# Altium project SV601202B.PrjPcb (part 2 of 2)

## Sheet SV601202B_CONNECTOR.SchDoc
size 431 x 279 mm; Date: Not shown in title block; ApprovedBy: Not shown in title block; CheckedBy: Not shown in title block; Author: Not shown in title block; CompanyName: Not shown in title block; Engineer: Not shown in title block; Organization: Not shown in title block; Address1: Not shown in title block; Address2: Not shown in title block; Address3: Not shown in title block; Address4: Not shown in title block; DocumentNumber: 1; Revision: Use project parameter SCH_Rev; SheetNumber: 2; SheetTotal: 3; PageSetup: Record=PageOptions¦CenterHorizontal=True¦CenterVertical=True¦PrintScale=1.00¦XCorrection=1.00¦YCorrection=1.00¦PrintKind=0¦BorderSize=5000000¦LeftOffset=0¦BottomOffset=0¦Orientation=2¦PaperLength=1000¦PaperWidth=1000¦Scale=100¦PaperSource=15¦PrintQuality=600¦MediaType=1¦DitherType=10¦PaperKind=Letter¦PrintScaleMode=1
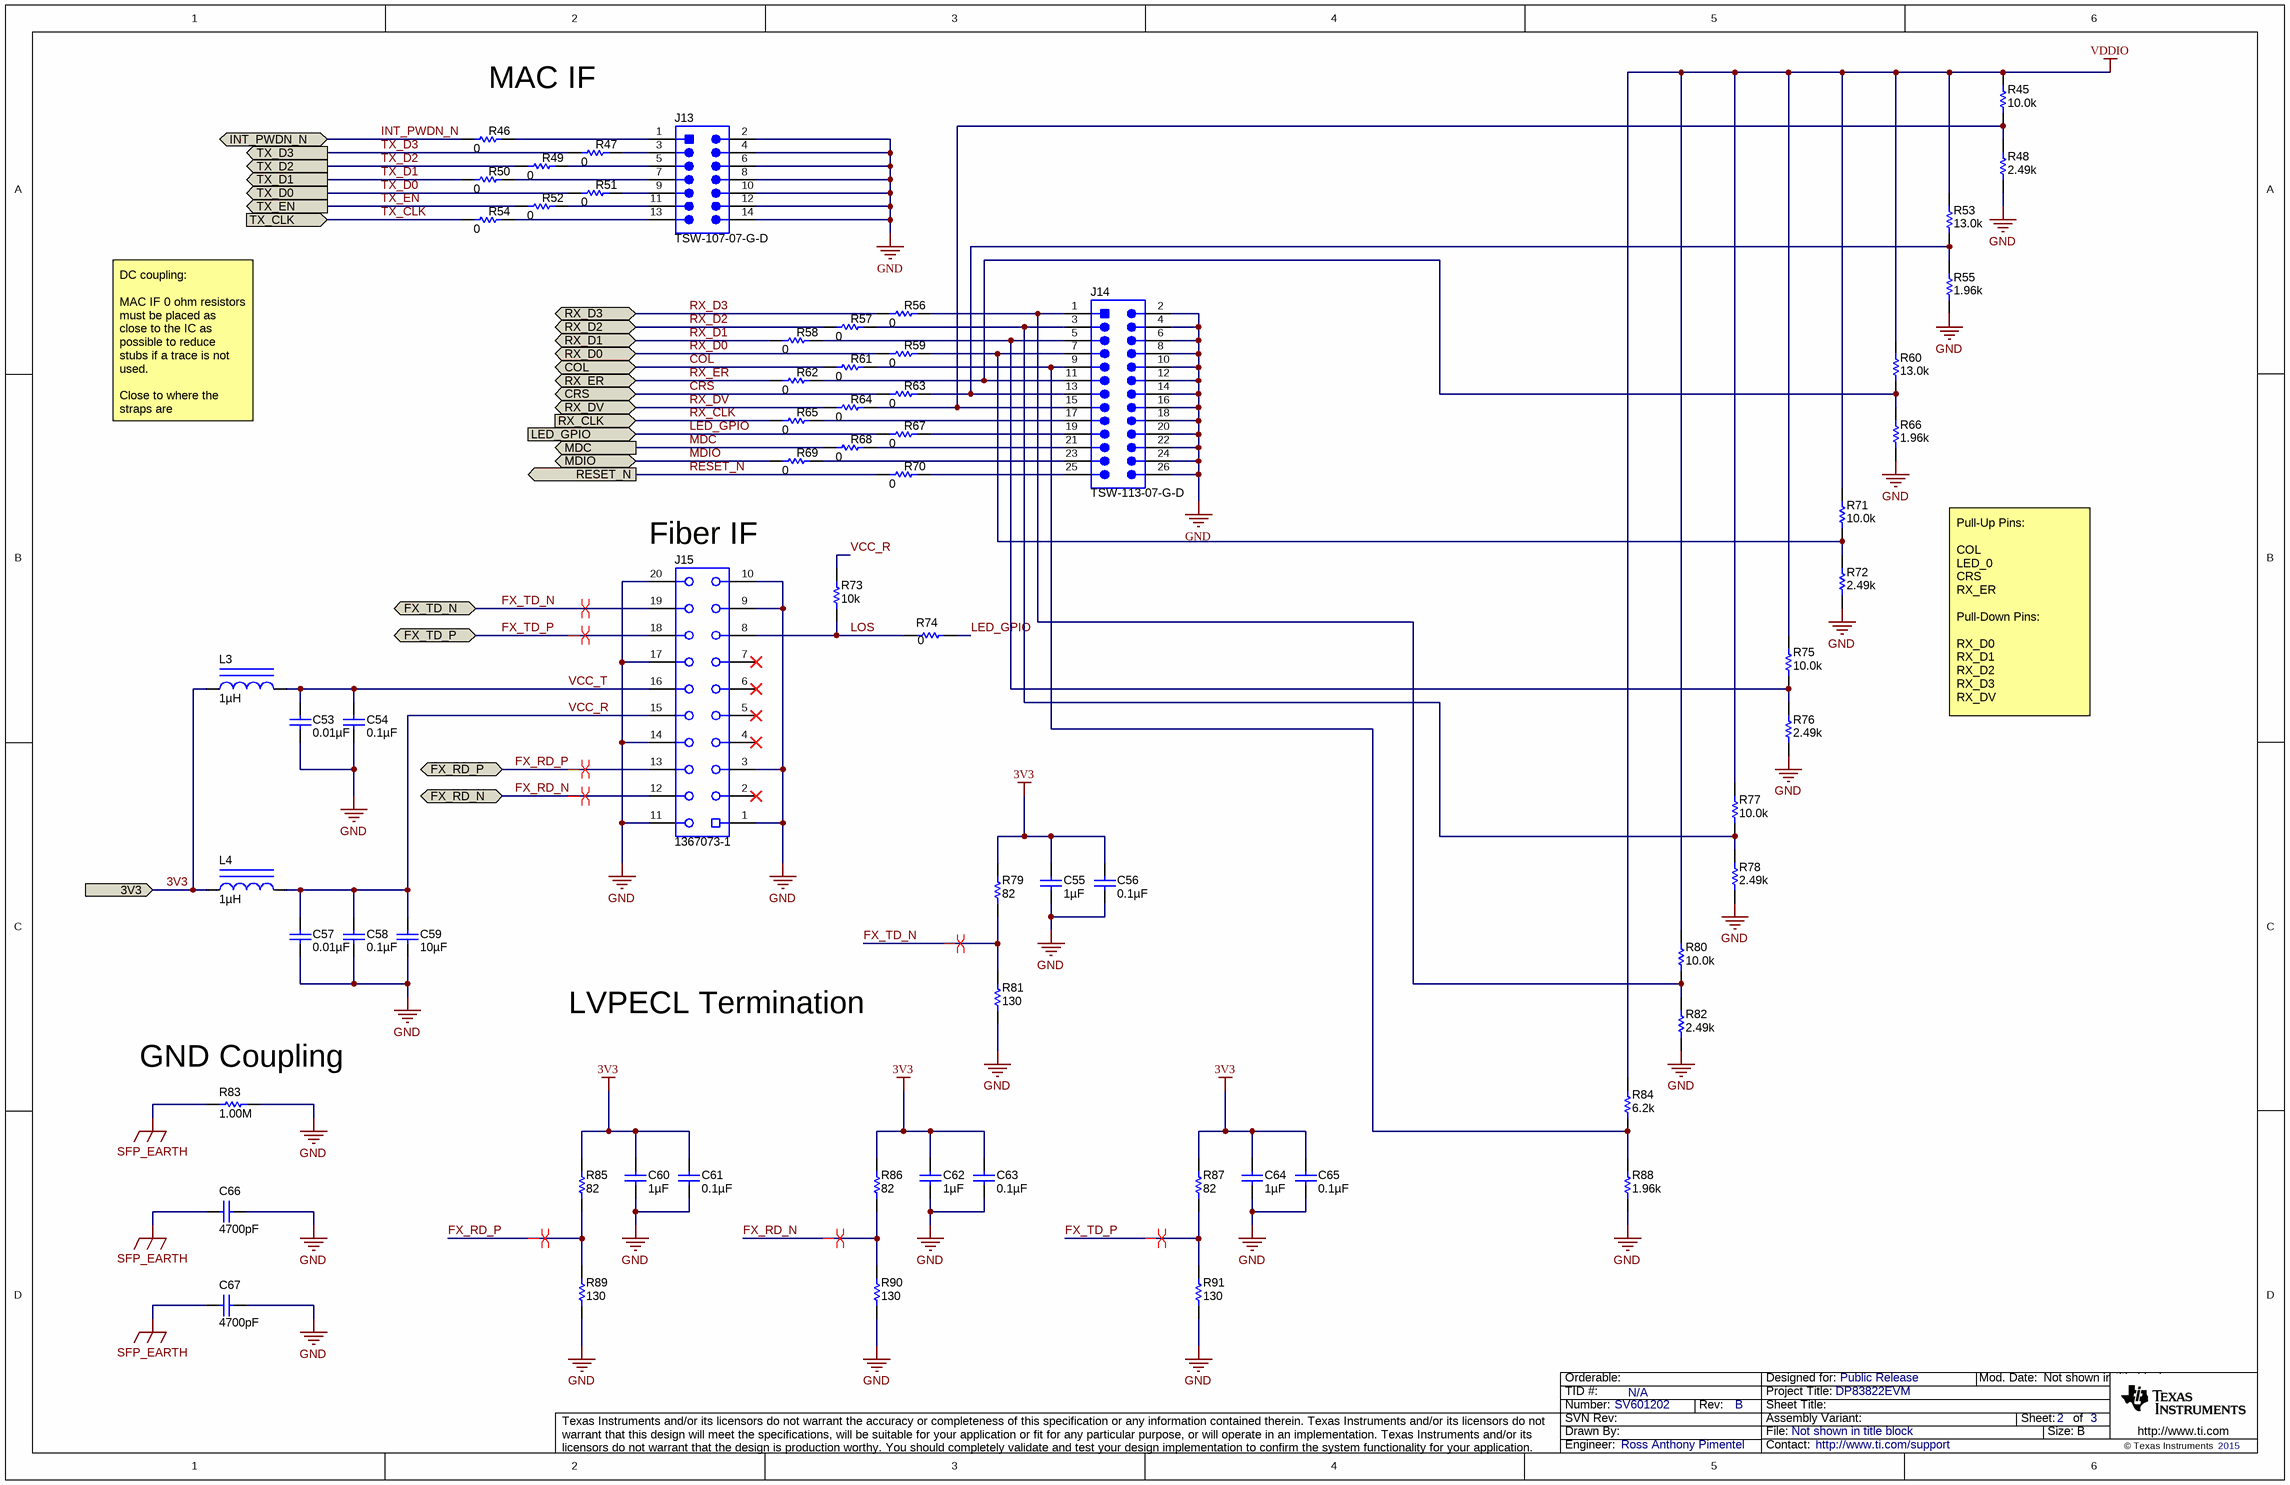
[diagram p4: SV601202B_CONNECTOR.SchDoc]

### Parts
C53  ValueDisplayed: 0.01µF  [0402]  (hidden comment: CGA2B3X7R1H103K050BB)
C54  ValueDisplayed: 0.1µF  [0402]  (hidden comment: GRM155R71C104KA88D)
C55  ValueDisplayed: 1µF  [0402]  (hidden comment: C1005X7S1A105K050BC)
C56  ValueDisplayed: 0.1µF  [0402]  (hidden comment: GRM155R71C104KA88D)
C57  ValueDisplayed: 0.01µF  [0402]  (hidden comment: CGA2B3X7R1H103K050BB)
C58  ValueDisplayed: 0.1µF  [0402]  (hidden comment: GRM155R71C104KA88D)
C59  ValueDisplayed: 10µF  [1210_280]  (hidden comment: CGA6P1X7R1E106M250AC)
C60  ValueDisplayed: 1µF  [0402]  (hidden comment: C1005X7S1A105K050BC)
C61  ValueDisplayed: 0.1µF  [0402]  (hidden comment: GRM155R71C104KA88D)
C62  ValueDisplayed: 1µF  [0402]  (hidden comment: C1005X7S1A105K050BC)
C63  ValueDisplayed: 0.1µF  [0402]  (hidden comment: GRM155R71C104KA88D)
C64  ValueDisplayed: 1µF  [0402]  (hidden comment: C1005X7S1A105K050BC)
C65  ValueDisplayed: 0.1µF  [0402]  (hidden comment: GRM155R71C104KA88D)
C66  ValueDisplayed: 4700pF  [1812_254]  (hidden comment: 1812GC472KAT1A)
C67  ValueDisplayed: 4700pF  [1812_254]  (hidden comment: 1812GC472KAT1A)
J13  TSW-107-07-G-D  [TSW-107-07-G-D]
J14  TSW-113-07-G-D  [TSW-113-07-G-D]
J15  1367073-1  [TE_1367073-1]
L3  ValueDisplayed: 1µH  [IFSC-0806AZ-01]  (hidden comment: IFSC0806AZER1R0M01)
L4  ValueDisplayed: 1µH  [IFSC-0806AZ-01]  (hidden comment: IFSC0806AZER1R0M01)
R45  ValueDisplayed: 10.0k  [0402]  (hidden comment: CRCW040210K0FKED)
R46  ValueDisplayed: 0  [0201L]  (hidden comment: ERJ-1GE0R00C)
R47  ValueDisplayed: 0  [0201L]  (hidden comment: ERJ-1GE0R00C)
R48  ValueDisplayed: 2.49k  [0402]  (hidden comment: CRCW04022K49FKED)
R49  ValueDisplayed: 0  [0201L]  (hidden comment: ERJ-1GE0R00C)
R50  ValueDisplayed: 0  [0201L]  (hidden comment: ERJ-1GE0R00C)
R51  ValueDisplayed: 0  [0201L]  (hidden comment: ERJ-1GE0R00C)
R52  ValueDisplayed: 0  [0201L]  (hidden comment: ERJ-1GE0R00C)
R53  ValueDisplayed: 13.0k  [0402]  (hidden comment: CRCW040213K0FKED)
R54  ValueDisplayed: 0  [0201L]  (hidden comment: ERJ-1GE0R00C)
R55  ValueDisplayed: 1.96k  [0402]  (hidden comment: CRCW04021K96FKED)
R56  ValueDisplayed: 0  [0201L]  (hidden comment: ERJ-1GE0R00C)
R57  ValueDisplayed: 0  [0201L]  (hidden comment: ERJ-1GE0R00C)
R58  ValueDisplayed: 0  [0201L]  (hidden comment: ERJ-1GE0R00C)
R59  ValueDisplayed: 0  [0201L]  (hidden comment: ERJ-1GE0R00C)
R60  ValueDisplayed: 13.0k  [0402]  (hidden comment: CRCW040213K0FKED)
R61  ValueDisplayed: 0  [0201L]  (hidden comment: ERJ-1GE0R00C)
R62  ValueDisplayed: 0  [0201L]  (hidden comment: ERJ-1GE0R00C)
R63  ValueDisplayed: 0  [0201L]  (hidden comment: ERJ-1GE0R00C)
R64  ValueDisplayed: 0  [0201L]  (hidden comment: ERJ-1GE0R00C)
R65  ValueDisplayed: 0  [0201L]  (hidden comment: ERJ-1GE0R00C)
R66  ValueDisplayed: 1.96k  [0402]  (hidden comment: CRCW04021K96FKED)
R67  ValueDisplayed: 0  [0201L]  (hidden comment: ERJ-1GE0R00C)
R68  ValueDisplayed: 0  [0201L]  (hidden comment: ERJ-1GE0R00C)
R69  ValueDisplayed: 0  [0201L]  (hidden comment: ERJ-1GE0R00C)
R70  ValueDisplayed: 0  [0201L]  (hidden comment: ERJ-1GE0R00C)
R71  ValueDisplayed: 10.0k  [0402]  (hidden comment: CRCW040210K0FKED)
R72  ValueDisplayed: 2.49k  [0402]  (hidden comment: CRCW04022K49FKED)
R73  ValueDisplayed: 10k  [0603]  (hidden comment: RC0603JR-0710KL)
R74  ValueDisplayed: 0  [0402]  (hidden comment: RC0402JR-070RL)
R75  ValueDisplayed: 10.0k  [0402]  (hidden comment: CRCW040210K0FKED)
R76  ValueDisplayed: 2.49k  [0402]  (hidden comment: CRCW04022K49FKED)
R77  ValueDisplayed: 10.0k  [0402]  (hidden comment: CRCW040210K0FKED)
R78  ValueDisplayed: 2.49k  [0402]  (hidden comment: CRCW04022K49FKED)
R79  ValueDisplayed: 82  [0402]  (hidden comment: CRCW040282R0JNED)
R80  ValueDisplayed: 10.0k  [0402]  (hidden comment: CRCW040210K0FKED)
R81  ValueDisplayed: 130  [0402]  (hidden comment: CRCW0402130RJNED)
R82  ValueDisplayed: 2.49k  [0402]  (hidden comment: CRCW04022K49FKED)
R83  ValueDisplayed: 1.00M  [1206]  (hidden comment: CRCW12061M00FKEA)
R84  ValueDisplayed: 6.2k  [0402]  (hidden comment: CRCW04026K20JNED)
R85  ValueDisplayed: 82  [0402]  (hidden comment: CRCW040282R0JNED)
R86  ValueDisplayed: 82  [0402]  (hidden comment: CRCW040282R0JNED)
R87  ValueDisplayed: 82  [0402]  (hidden comment: CRCW040282R0JNED)
R88  ValueDisplayed: 1.96k  [0402]  (hidden comment: CRCW04021K96FKED)
R89  ValueDisplayed: 130  [0402]  (hidden comment: CRCW0402130RJNED)
R90  ValueDisplayed: 130  [0402]  (hidden comment: CRCW0402130RJNED)
R91  ValueDisplayed: 130  [0402]  (hidden comment: CRCW0402130RJNED)

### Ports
3V3, COL (bidir), CRS (bidir), FX_RD_N (bidir), FX_RD_P (bidir), FX_TD_N (bidir), FX_TD_P (bidir), INT_PWDN_N (bidir), LED_GPIO (in), MDC (out), MDIO (bidir), RESET_N (out), RX_CLK (in), RX_D0 (bidir), RX_D1 (bidir), RX_D2 (bidir), RX_D3 (bidir), RX_DV (bidir), RX_ER (bidir), TX_CLK (in), TX_D0 (out), TX_D1 (out), TX_D2 (out), TX_D3 (out), TX_EN (out)

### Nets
3V3: C55.1 C56.1 C60.1 C61.1 C62.1 C63.1 C64.1 C65.1 L3.1 L4.1 R79.2 R85.2 R86.2 R87.2 ; port 3V3
GND: C53.2 C54.2 C55.2 C56.2 C57.2 C58.2 C59.2 C60.2 C61.2 C62.2 C63.2 C64.2 C65.2 C66.1 C67.1 J13.2 J13.4 J13.6 J13.8 J13.10 J13.12 J13.14 J14.2 J14.4 J14.6 J14.8 J14.10 J14.12 J14.14 J14.16 J14.18 J14.20 J14.22 J14.24 J14.26 J15.1 J15.3 J15.9 J15.10 J15.11 J15.14 J15.17 J15.20 R48.1 R55.1 R66.1 R72.1 R76.1 R78.1 R81.1 R82.1 R83.2 R88.1 R89.1 R90.1 R91.1
SFP_EARTH: C66.2 C67.2 R83.1
VDDIO: R45.2 R53.2 R60.2 R71.2 R75.2 R77.2 R80.2 R84.2
COL: R61.2 ; port COL
CRS: R63.2 ; port CRS
FX_RD_N: J15.12 R86.1 R90.2 ; port FX_RD_N
FX_RD_P: J15.13 R85.1 R89.2 ; port FX_RD_P
FX_TD_N: J15.19 R79.1 R81.2 ; port FX_TD_N
FX_TD_P: J15.18 R87.1 R91.2 ; port FX_TD_P
INT_PWDN_N: R46.2 ; port INT_PWDN_N
LED_GPIO: R67.2 R74.1 ; port LED_GPIO
LOS: J15.8 R73.1 R74.2
MDC: R68.2 ; port MDC
MDIO: R69.2 ; port MDIO
RESET_N: R70.2 ; port RESET_N
RX_CLK: R65.2 ; port RX_CLK
RX_D0: R59.2 ; port RX_D0
RX_D1: R58.2 ; port RX_D1
RX_D2: R57.2 ; port RX_D2
RX_D3: R56.2 ; port RX_D3
RX_DV: R64.2 ; port RX_DV
RX_ER: R62.2 ; port RX_ER
TX_CLK: R54.2 ; port TX_CLK
TX_D0: R51.2 ; port TX_D0
TX_D1: R50.2 ; port TX_D1
TX_D2: R49.2 ; port TX_D2
TX_D3: R47.2 ; port TX_D3
TX_EN: R52.2 ; port TX_EN
VCC_R: C57.1 C58.1 C59.1 J15.15 L4.2 R73.2
VCC_T: C53.1 C54.1 J15.16 L3.2
NetJ13_1: J13.1 R46.1
NetJ13_3: J13.3 R47.1
NetJ13_5: J13.5 R49.1
NetJ13_7: J13.7 R50.1
NetJ13_9: J13.9 R51.1
NetJ13_11: J13.11 R52.1
NetJ13_13: J13.13 R54.1
NetJ14_1: J14.1 R56.1 R80.1 R82.2
NetJ14_3: J14.3 R57.1 R77.1 R78.2
NetJ14_5: J14.5 R58.1 R75.1 R76.2
NetJ14_7: J14.7 R59.1 R71.1 R72.2
NetJ14_9: J14.9 R61.1 R84.1 R88.2
NetJ14_11: J14.11 R60.1 R62.1 R66.2
NetJ14_13: J14.13 R53.1 R55.2 R63.1
NetJ14_15: J14.15 R45.1 R48.2 R64.1
NetJ14_17: J14.17 R65.1
NetJ14_19: J14.19 R67.1
NetJ14_21: J14.21 R68.1
NetJ14_23: J14.23 R69.1
NetJ14_25: J14.25 R70.1

Not connected (* = marked no-connect by the designer): J15 2* 4* 5* 6* 7*

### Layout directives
differential pair: FX_RD_N, FX_RD_P, FX_TD_N, FX_TD_P

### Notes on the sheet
- MAC IF
- DC coupling:
  MAC IF 0 ohm resistors must be placed as close to the IC as possible to reduce stubs if a trace is not used.
  Close to where the straps are
- (near J15) Fiber IF
- Pull-Up Pins:
  COL
  LED_0
  CRS
  RX_ER
  Pull-Down Pins:
  RX_D0
  RX_D1
  RX_D2
  RX_D3
  RX_DV
- LVPECL Termination
- (near R83) GND Coupling

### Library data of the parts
C53 C57 = CGA2B3X7R1H103K050BB: CAP, CERM, 0.01 µF, 50 V, +/- 10%, X7R, AEC-Q200 Grade 1, 0402; Manufacturer: TDK; Polarized: N; CompType: Capacitor; Value: 0.01uF; U/M: EA; Cap_F: 0.00000001; Tolerance_%: 10; Value1: Unknown; VDC_V: 50; Value2: 50V; TaMin_C: -55; TaMax_C: 125; AEC Category: Q200; AEC Qualified: Y; AEC Grade: 1
C54 C56 C58 C61 C63 C65 = GRM155R71C104KA88D: CAP, CERM, 0.1 µF, 16 V, +/- 10%, X7R, 0402; Manufacturer: MuRata; Polarized: N; CompType: Capacitor; Value: 0.1uF; U/M: EA; Cap_F: 0.0000001; Tolerance_%: 10; Value1: Unknown; VDC_V: 16; Value2: 16V; TaMin_C: -55; TaMax_C: 125
C55 C60 C62 C64 = C1005X7S1A105K050BC: CAP, CERM, 1 µF, 10 V, +/- 10%, X7S, 0402; Manufacturer: TDK; Polarized: N; CompType: Capacitor; Value: 1uF; U/M: EA; Cap_F: 0.000001; Tolerance_%: 10; Value1: Unknown; Value2: 10V; TaMin_C: -55; TaMax_C: 125
C59 = CGA6P1X7R1E106M250AC: CAP, CERM, 10 µF, 25 V, +/- 20%, X7R, AEC-Q200 Grade 1, 1210; Manufacturer: TDK; Polarized: N; CompType: Capacitor; Value: 10uF; U/M: EA; Cap_F: 0.00001; Tolerance_%: 20; Value1: Unknown; VDC_V: 25; Value2: 25V; TaMin_C: -55; TaMax_C: 125; Cap_Case: 1210; AEC Category: Q200; AEC Qualified: Y; AEC Grade: 1
C66 C67 = 1812GC472KAT1A: CAP, CERM, 4700 pF, 2000 V, +/- 10%, X7R, 1812; Manufacturer: AVX; Polarized: N; CompType: Capacitor; Value: 4700pF; U/M: EA; Cap_F: 0.0000000047; Tolerance_%: 10; Value1: Unknown; VDC_V: 2000; Value2: 2000V; TaMin_C: -55; TaMax_C: 125; Cap_Case: 1812
J13 = TSW-107-07-G-D: Header, 100mil, 7x2, Gold, TH; Manufacturer: Samtec; SymbolCreator: a0412235; Pitch_mm: 2.54; Gender: Male; Shrouded: N; Row_Count: 2; Current_A: 6.3; Voltage_V: 550; Cert_CSA: Y
J14 = TSW-113-07-G-D: Header, 100mil, 13x2, Gold, TH; Manufacturer: Samtec; SymbolCreator: a0412235; Pitch_mm: 2.54; Gender: Male; Shrouded: N; Row_Count: 2; Current_A: 6.3; Voltage_V: 550; Cert_CSA: Y
J15 = 1367073-1: Receptacle, 0.8mm, 10x2, Gold, R/A, SMT; Manufacturer: TE Connectivity; SymbolCreator: a0412235; U/M: EA
L3 L4 = IFSC0806AZER1R0M01: Inductor, Shielded, Ferrite, 1 µH, 1.6 A, 0.115 ohm, SMD; Manufacturer: Vishay-Dale; Value: 1uH; Ind_H: 1.0E-6; Imax_A: 1.6; Irms: 1.6A @ 40C rise; Isat: 1.88A @ 30% inductance drop; DCR_ohm: 0.115; Value2: 1.6A
R45 R71 R75 R77 R80 = CRCW040210K0FKED: RES, 10.0 k, 1%, 0.063 W, 0402; Manufacturer: Vishay-Dale; CompType: Resistor; Value: 10.0k; Res_ohm: 10000; Value_Code: 10k0; Tolerance_%: 1; Power_W: 0.063; Value2: 0.063W; VDC_V: 50; TempCo: 100 ppm/C; EIA_Code: E96; U/M: EA; AEC Category: Q200
R46 R47 R49-R52 R54 R56-R59 R61-R65 R67-R70 = ERJ-1GE0R00C: RES, 0, 5%, 0.05 W, 0201; Manufacturer: Panasonic; CompType: Resistor; Value: 0; Value_Code: 0000; Tolerance_%: 5; Power_W: 0.05; Value2: 0.05W; VDC_V: 15; TempCo: 600 ppm/C; EIA_Code: E24; U/M: EA; AEC Category: Q200
R48 R72 R76 R78 R82 = CRCW04022K49FKED: RES, 2.49 k, 1%, 0.063 W, 0402; Manufacturer: Vishay-Dale; CompType: Resistor; Value: 2.49k; Res_ohm: 2490; Value_Code: 2k49; Tolerance_%: 1; Power_W: 0.063; Value2: 0.063W; VDC_V: 50; TempCo: 100 ppm/C; EIA_Code: E96; U/M: EA; AEC Category: Q200
R53 R60 = CRCW040213K0FKED: RES, 13.0 k, 1%, 0.063 W, 0402; Manufacturer: Vishay-Dale; CompType: Resistor; Value: 13.0k; Res_ohm: 13000; Value_Code: 13k0; Tolerance_%: 1; Power_W: 0.063; Value2: 0.063W; VDC_V: 50; TempCo: 100 ppm/C; EIA_Code: E96; U/M: EA; AEC Category: Q200
R55 R66 R88 = CRCW04021K96FKED: RES, 1.96 k, 1%, 0.063 W, 0402; Manufacturer: Vishay-Dale; CompType: Resistor; Value: 1.96k; Res_ohm: 1960; Value_Code: 1k96; Tolerance_%: 1; Power_W: 0.063; Value2: 0.063W; VDC_V: 50; TempCo: 100 ppm/C; EIA_Code: E96; U/M: EA; AEC Category: Q200
R73 = RC0603JR-0710KL: RES, 10 k, 5%, 0.1 W, 0603; Manufacturer: Yageo America; CompType: Resistor; Value: 10k; Res_ohm: 10000; Value_Code: 10k0; Tolerance_%: 5; Power_W: 0.1; Value2: 0.1W; VDC_V: 50; TempCo: 100 ppm/C; EIA_Code: E24; U/M: EA; AEC Category: Q200
R74 = RC0402JR-070RL: RES, 0, 5%, 0.063 W, 0402; Manufacturer: Yageo America; CompType: Resistor; Value: 0; Value_Code: 0000; Tolerance_%: 5; Power_W: 0.063; Value2: 0.063W; VDC_V: 50; TempCo: 200 ppm/C; EIA_Code: E24; U/M: EA
R79 R85-R87 = CRCW040282R0JNED: RES, 82, 5%, 0.063 W, 0402; Manufacturer: Vishay-Dale; CompType: Resistor; Value: 82; Value_Code: 82R0; Tolerance_%: 5; Power_W: 0.063; Value2: 0.063W; VDC_V: 50; TempCo: 200 ppm/C; EIA_Code: E24; U/M: EA; AEC Category: Q200
R81 R89-R91 = CRCW0402130RJNED: RES, 130, 5%, 0.063 W, 0402; Manufacturer: Vishay-Dale; CompType: Resistor; Value: 130; Value_Code: 130R; Tolerance_%: 5; Power_W: 0.063; Value2: 0.063W; VDC_V: 50; TempCo: 200 ppm/C; EIA_Code: E24; U/M: EA; AEC Category: Q200
R83 = CRCW12061M00FKEA: RES, 1.00 M, 1%, 0.25 W, 1206; Manufacturer: Vishay-Dale; CompType: Resistor; Value: 1.00Meg; Res_ohm: 1000000; Value_Code: 1M00; Tolerance_%: 1; Power_W: 0.25; Value2: 0.25W; VDC_V: 200; TempCo: 100 ppm/C; EIA_Code: E96; U/M: EA; AEC Category: Q200
R84 = CRCW04026K20JNED: RES, 6.2 k, 5%, 0.063 W, 0402; Manufacturer: Vishay-Dale; CompType: Resistor; Value: 6.2k; Res_ohm: 6200; Value_Code: 6k20; Tolerance_%: 5; Power_W: 0.063; Value2: 0.063W; VDC_V: 50; TempCo: 200 ppm/C; EIA_Code: E24; U/M: EA; AEC Category: Q200

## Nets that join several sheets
3V3: SV601202B_AFE (11 pins), SV601202B_POWER_BLOCK (J6.6 J6.8), SV601202B_CONNECTOR (14 pins)
+1V8: SV601202B_MAIN_BLOCK (5 pins), SV601202B_POWER_BLOCK (C35.1 R14.2 U3.4)
AVD: SV601202B_MAIN_BLOCK (8 pins), SV601202B_POWER_BLOCK (D1.1 J6.10 J6.12)
EARTH: SV601202B_Hardware (M1.1), SV601202B_AFE (11 pins)
GND: SV601202B_Hardware (C68.2 C69.2), SV601202B_AFE (10 pins), SV601202B_MAIN_BLOCK (43 pins), SV601202B_POWER_BLOCK (30 pins), SV601202B_CONNECTOR (56 pins)
SFP_EARTH: SV601202B_Hardware (21 pins), SV601202B_CONNECTOR (C66.2 C67.2 R83.1)
VDDIO: SV601202B_MAIN_BLOCK (13 pins), SV601202B_POWER_BLOCK (7 pins), SV601202B_CONNECTOR (8 pins)
COL: SV601202B_MAIN_BLOCK (U2.29), SV601202B_CONNECTOR (R61.2)
CRS: SV601202B_MAIN_BLOCK (U2.27), SV601202B_CONNECTOR (R63.2)
FX_RD_N: SV601202B_AFE (R36.2), SV601202B_CONNECTOR (J15.12 R86.1 R90.2)
FX_RD_P: SV601202B_AFE (R41.2), SV601202B_CONNECTOR (J15.13 R85.1 R89.2)
FX_TD_N: SV601202B_AFE (R42.2), SV601202B_CONNECTOR (J15.19 R79.1 R81.2)
FX_TD_P: SV601202B_AFE (R44.2), SV601202B_CONNECTOR (J15.18 R87.1 R91.2)
INT_PWDN_N: SV601202B_MAIN_BLOCK (C26.1 R6.1 R9.2 U2.8), SV601202B_CONNECTOR (R46.2)
LED_0: SV601202B_MAIN_BLOCK (U2.17), SV601202B_POWER_BLOCK (J10.2)
LED_GPIO: SV601202B_MAIN_BLOCK (U2.24), SV601202B_POWER_BLOCK (J11.2), SV601202B_CONNECTOR (R67.2 R74.1)
MDC: SV601202B_MAIN_BLOCK (U2.20), SV601202B_CONNECTOR (R68.2)
MDIO: SV601202B_MAIN_BLOCK (R5.1 U2.19), SV601202B_CONNECTOR (R69.2)
RESET_N: SV601202B_MAIN_BLOCK (C27.1 R8.1 S1.1 U2.18), SV601202B_CONNECTOR (R70.2)
RX_CLK: SV601202B_MAIN_BLOCK (U2.25), SV601202B_CONNECTOR (R65.2)
RX_D0: SV601202B_MAIN_BLOCK (U2.30), SV601202B_CONNECTOR (R59.2)
RX_D1: SV601202B_MAIN_BLOCK (U2.31), SV601202B_CONNECTOR (R58.2)
RX_D2: SV601202B_MAIN_BLOCK (U2.32), SV601202B_CONNECTOR (R57.2)
RX_D3: SV601202B_MAIN_BLOCK (R7.2 U2.1), SV601202B_CONNECTOR (R56.2)
RX_DV: SV601202B_MAIN_BLOCK (U2.26), SV601202B_CONNECTOR (R64.2)
RX_ER: SV601202B_MAIN_BLOCK (U2.28), SV601202B_CONNECTOR (R62.2)
RXD_N: SV601202B_AFE (5 pins), SV601202B_MAIN_BLOCK (U2.9)
RXD_P: SV601202B_AFE (5 pins), SV601202B_MAIN_BLOCK (U2.10)
TX_CLK: SV601202B_MAIN_BLOCK (U2.2), SV601202B_CONNECTOR (R54.2)
TX_D0: SV601202B_MAIN_BLOCK (U2.4), SV601202B_CONNECTOR (R51.2)
TX_D1: SV601202B_MAIN_BLOCK (U2.5), SV601202B_CONNECTOR (R50.2)
TX_D2: SV601202B_MAIN_BLOCK (U2.6), SV601202B_CONNECTOR (R49.2)
TX_D3: SV601202B_MAIN_BLOCK (U2.7), SV601202B_CONNECTOR (R47.2)
TX_EN: SV601202B_MAIN_BLOCK (U2.3), SV601202B_CONNECTOR (R52.2)
TXD_N: SV601202B_AFE (5 pins), SV601202B_MAIN_BLOCK (U2.11)
TXD_P: SV601202B_AFE (5 pins), SV601202B_MAIN_BLOCK (U2.12)

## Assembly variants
001: not fitted C4 C5 C12 C14 C15 C19 C21 C22 C26 C27 C29 C40 C47 C48 C49 C50 C52 C53 C54 C55 C56 C57 C58 C59 C60 C61 C62 C63 C64 C65 C67 GND2 H1 J1 J4 J15 L3 L4 R4 R7 R8 R9 R11 R36 R41 R42 R43 R44 R45 R48 R53 R55 R60 R66 R71 R72 R73 R74 R75 R76 R77 R78 R79 R80 R81 R82 R83 R84 R85 R86 R87 R88 R89 R90 R91 R93 R94 U6 U7 V+2
002: not fitted C4 C5 C12 C14 C18 C19 C21 C25 C26 C27 C29 C40 C41 C42 C43 C44 C45 C46 C52 C55 C56 C60 C61 C62 C63 C64 C65 C67 GND2 J1 J4 J12 R4 R7 R8 R9 R11 R28 R29 R30 R31 R32 R33 R34 R35 R43 R45 R48 R53 R55 R60 R66 R71 R72 R73 R74 R75 R76 R77 R78 R79 R80 R81 R82 R83 R84 R85 R86 R87 R88 R89 R90 R91 R93 R94 T2 U6 U7 V+2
